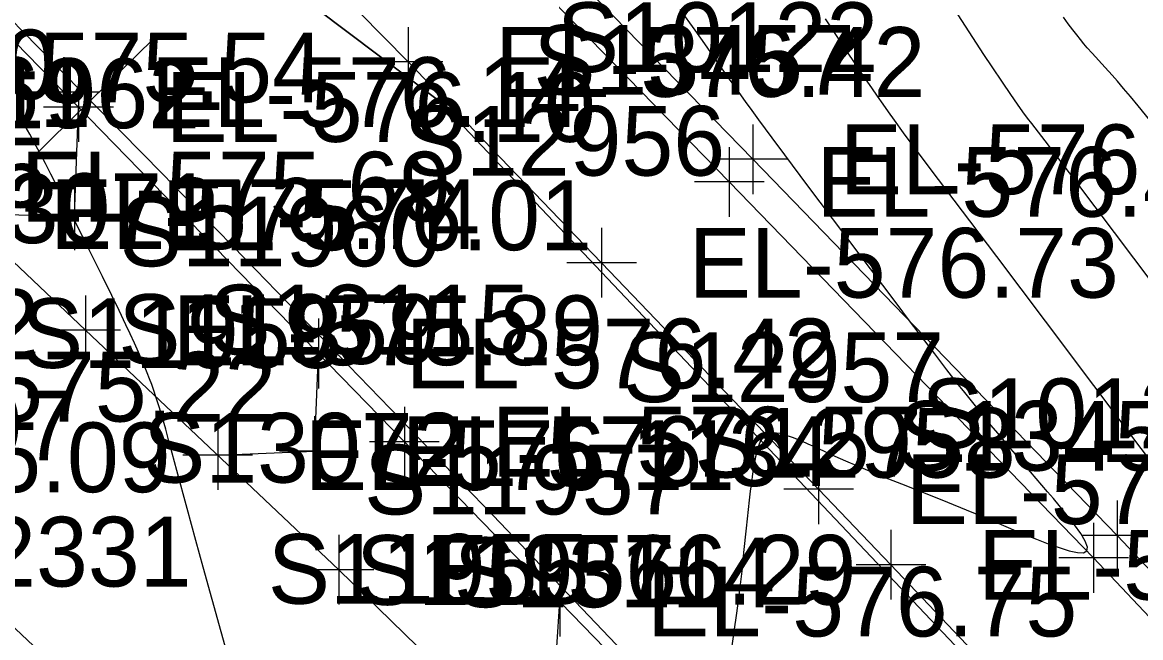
# Model space of a CAD drawing. Extents: x 1729869 to 1735532, y 648588 to 653771.
# Drawn here: x 1731155.8 to 1731220, y 652078.5 to 652113.8 of the extents above; entities that cross this region are included whole.
import ezdxf

# ---------------------------------------------------------------- set-up
doc = ezdxf.new("R2010")
doc.units = 0
for name, color, linetype in [('SURVEY - CENTERLINE - Preliminary', 7, 'Continuous'), ('SURVEY - CENTERLINE - Preliminary Text', 7, 'Continuous'), ('SURVEY - CONTOURS - Index with Text', 7, 'Continuous'), ('SURVEY - CONTOURS - Intermediate with optional Text', 7, 'Continuous'), ('SURVEY - DRAINAGE - Area Shapes', 7, 'Continuous'), ('SURVEY - DRAINAGE - Area Shapes Text', 7, 'Continuous'), ('SURVEY - DRAINAGE - Storm Sewer - Points - Numbers', 7, 'Continuous'), ('SURVEY - DTM - Breaklines', 7, 'Continuous'), ('SURVEY - DTM - Breaklines - Points - Elevations', 7, 'Continuous'), ('SURVEY - DTM - Breaklines - Points - Locators', 7, 'Continuous'), ('SURVEY - DTM - Breaklines - Points - Numbers', 7, 'Continuous'), ('SURVEY - ROADSIDE BARRIERS - Points - Elevations', 7, 'Continuous'), ('SURVEY - TRAFFIC CONTROL - Pavement Marking - Points - Elevations', 7, 'Continuous'), ('SURVEY - TRAFFIC CONTROL - Pavement Marking - Points - Locators', 7, 'Continuous'), ('SURVEY - TRAFFIC CONTROL - Pavement Marking - Points - Numbers', 7, 'Continuous'), ('SURVEY - TRAFFIC CONTROL - Pavement Marking with Text', 7, 'Continuous'), ('SURVEY - TRANSPORTATION - Features', 7, 'Continuous'), ('SURVEY - TRANSPORTATION - Features - Points - Elevations', 7, 'Continuous'), ('SURVEY - TRANSPORTATION - Features - Points - Locators', 7, 'Continuous'), ('SURVEY - TRANSPORTATION - Features - Points - Numbers', 7, 'Continuous'), ('SURVEY - TRANSPORTATION - Roads', 7, 'Continuous'), ('SURVEY - TRANSPORTATION - Roads - Points - Elevations', 7, 'Continuous'), ('SURVEY - TRANSPORTATION - Roads - Points - Locators', 7, 'Continuous'), ('SURVEY - TRANSPORTATION - Roads - Points - Numbers', 7, 'Continuous')]:
    doc.layers.add(name, color=color, linetype=linetype)

msp = doc.modelspace()

# ---------------------------------------------------------------- linework, layer by layer
at = {"layer": 'SURVEY - CENTERLINE - Preliminary'}
msp.add_arc((1729018.342, 650008.232), 3000, 36.727042, 45.05905, dxfattribs=at)
at = {"layer": 'SURVEY - CENTERLINE - Preliminary Text'}
for q in [(1731163.301, 652112.792), (1731156.164, 652105.788)]:
    msp.add_line((1731159.733, 652109.29), q, dxfattribs=at)
at = {"layer": 'SURVEY - CONTOURS - Index with Text'}
msp.add_lwpolyline([(1731222.414, 652105.812), (1731219.833, 652108.997), (1731219.393, 652109.525), (1731218.999, 652109.991), (1731218.647, 652110.4), (1731218.34, 652110.75), (1731217.94, 652111.196), (1731217.201, 652112.002), (1731216.919, 652112.319), (1731216.727, 652112.543), (1731216.526, 652112.786), (1731216.313, 652113.053), (1731216.082, 652113.354), (1731215.832, 652113.69), (1731215.559, 652114.066)], dxfattribs=at)
at = {"layer": 'SURVEY - CONTOURS - Intermediate with optional Text'}
for points in [[(1731196.464, 652077.466), (1731196.703, 652079.098), (1731196.778, 652079.617), (1731196.891, 652080.442), (1731196.97, 652081.069), (1731197.044, 652081.694), (1731197.128, 652082.456), (1731197.22, 652083.365), (1731197.36, 652084.758), (1731197.415, 652085.295), (1731197.474, 652085.832), (1731197.534, 652086.363), (1731197.598, 652086.885), (1731197.664, 652087.391), (1731197.734, 652087.878), (1731197.789, 652088.231), (1731197.848, 652088.568), (1731197.879, 652088.729), (1731197.911, 652088.886), (1731197.978, 652089.168), (1731198.053, 652089.426), (1731198.14, 652089.657), (1731198.241, 652089.855), (1731198.358, 652090.017), (1731198.495, 652090.136), (1731198.624, 652090.202), (1731198.767, 652090.239), (1731198.924, 652090.25), (1731199.093, 652090.238), (1731199.273, 652090.207), (1731199.464, 652090.16), (1731199.575, 652090.127), (1731199.689, 652090.09), (1731199.805, 652090.049), (1731200.047, 652089.959), (1731200.172, 652089.909), (1731200.518, 652089.766), (1731200.879, 652089.609), (1731201.255, 652089.441), (1731202.437, 652088.901), (1731203.052, 652088.627), (1731203.677, 652088.355), (1731204.311, 652088.087), (1731204.789, 652087.89), (1731205.272, 652087.695), (1731206.253, 652087.306), (1731208.007, 652086.613), (1731208.908, 652086.251), (1731209.976, 652085.814), (1731211.092, 652085.351), (1731212.829, 652084.62), (1731213.613, 652084.295), (1731214.004, 652084.137), (1731214.673, 652083.876), (1731215.306, 652083.648), (1731215.875, 652083.472), (1731216.35, 652083.369), (1731216.702, 652083.357), (1731216.903, 652083.457), (1731216.931, 652083.684), (1731216.804, 652084.023), (1731216.55, 652084.452), (1731216.195, 652084.952), (1731215.768, 652085.499), (1731215.297, 652086.075), (1731214.974, 652086.46), (1731214.646, 652086.846), (1731213.327, 652088.384), (1731212.927, 652088.853), (1731212.535, 652089.315), (1731212.152, 652089.77), (1731211.779, 652090.218), (1731211.414, 652090.658), (1731211.059, 652091.091), (1731210.657, 652091.586), (1731210.27, 652092.069), (1731209.896, 652092.538), (1731209.537, 652092.993), (1731208.865, 652093.854), (1731208.167, 652094.759), (1731207.215, 652096.007), (1731206.78, 652096.581), (1731205.887, 652097.763), (1731200.886, 652104.406), (1731199.561, 652106.177), (1731198.839, 652107.148), (1731198.072, 652108.191), (1731197.692, 652108.713), (1731197.314, 652109.236), (1731196.938, 652109.761), (1731196.247, 652110.738), (1731194.841, 652112.737), (1731194.423, 652113.326), (1731193.568, 652114.518)], [(1731222.791, 652085.638), (1731214.52, 652096.635), (1731211.724, 652100.351), (1731210.186, 652102.387), (1731207.959, 652105.32), (1731207.174, 652106.363), (1731206.644, 652107.077), (1731206.37, 652107.45), (1731205.85, 652108.168), (1731205.509, 652108.645), (1731205.204, 652109.078), (1731204.885, 652109.535), (1731204.55, 652110.019), (1731204.198, 652110.533), (1731203.827, 652111.08), (1731202.901, 652112.467), (1731201.901, 652113.981)], [(1731231.504, 652084.417), (1731219.588, 652100.253), (1731216.262, 652104.666), (1731215.17, 652106.108), (1731214.495, 652106.99), (1731213.73, 652107.976), (1731213.496, 652108.285), (1731213.231, 652108.644), (1731212.918, 652109.082), (1731212.529, 652109.64), (1731212.046, 652110.35), (1731211.455, 652111.233), (1731210.992, 652111.932), (1731209.502, 652114.207)], [(1731167.742, 652076.973), (1731166.193, 652082.52), (1731165.769, 652084.056), (1731165.268, 652085.89), (1731164.682, 652088.07), (1731164.412, 652089.076), (1731164.226, 652089.765), (1731164.039, 652090.443), (1731163.851, 652091.1), (1731163.665, 652091.723), (1731163.481, 652092.303), (1731163.36, 652092.659), (1731163.238, 652093), (1731163.114, 652093.331), (1731162.975, 652093.684), (1731162.903, 652093.861), (1731162.695, 652094.36), (1731162.474, 652094.869), (1731162.243, 652095.386), (1731162.003, 652095.907), (1731161.758, 652096.431), (1731161.368, 652097.247), (1731160.944, 652098.119), (1731160.407, 652099.209), (1731159.653, 652100.727), (1731158.705, 652102.618), (1731158.064, 652103.885), (1731157.764, 652104.473), (1731157.455, 652105.073), (1731157.139, 652105.679), (1731156.818, 652106.285), (1731156.494, 652106.887), (1731156.237, 652107.356), (1731155.978, 652107.821), (1731155.703, 652108.301)]]:
    msp.add_lwpolyline(points, dxfattribs=at)
at = {"layer": 'SURVEY - DRAINAGE - Area Shapes'}
msp.add_lwpolyline([(1731097.142, 652171.409), (1731011.148, 652256.97), (1730865.03, 652403.158), (1730749.606, 652518.939), (1730781.764, 652550.883), (1730851.291, 652571.58), (1730949.072, 652515.98), (1730982.838, 652438.563), (1731020.351, 652368.14), (1731165.291, 652192.393), (1731281.807, 652137.032), (1731316.797, 652088.672), (1731252.279, 652032.718), (1731179.777, 652109.245)], close=True, dxfattribs=at)
at = {"layer": 'SURVEY - DRAINAGE - Area Shapes Text'}
msp.add_lwpolyline([(1731252.279, 652032.718), (1731252.279, 652032.718), (1731331.927, 651940.868), (1731382.756, 651879.672), (1731447.67, 651794.75), (1731482.093, 651747.619), (1731463.009, 651708.574), (1731417.334, 651769.604), (1731372.727, 651826.43), (1731331.142, 651879.707), (1731270.184, 651948.802), (1731219.221, 652002.428), (1731149.8, 652071.308), (1731071.45, 652144.137), (1731094.843, 652173.647), (1731097.142, 652171.409), (1731179.777, 652109.245)], close=True, dxfattribs=at)
at = {"layer": 'SURVEY - DTM - Breaklines'}
msp.add_lwpolyline([(1731035.462, 652269.556), (1731036.254, 652268.75), (1731049.78, 652255.258), (1731071.01, 652234.055), (1731092.233, 652212.831), (1731113.392, 652191.515), (1731134.61, 652170.281), (1731155.653, 652148.89), (1731176.704, 652127.515), (1731197.722, 652105.922), (1731218.638, 652084.352), (1731239.234, 652062.543), (1731259.779, 652040.444), (1731279.977, 652018.028), (1731278.681, 652016.879)], dxfattribs=at)
at = {"layer": 'SURVEY - DTM - Breaklines - Points - Locators'}
for p, q in [((1731197.722, 652107.922), (1731197.722, 652103.922)), ((1731199.722, 652105.922), (1731195.722, 652105.922)), ((1731218.638, 652086.352), (1731218.638, 652082.352)), ((1731220.638, 652084.352), (1731216.638, 652084.352))]:
    msp.add_line(p, q, dxfattribs=at)
at = {"layer": 'SURVEY - TRAFFIC CONTROL - Pavement Marking - Points - Locators'}
for p, q in [((1731159.036, 652110.921), (1731159.036, 652106.921)), ((1731161.036, 652108.921), (1731157.036, 652108.921)), ((1731158.811, 652104.708), (1731158.811, 652100.708)), ((1731160.811, 652102.708), (1731156.811, 652102.708)), ((1731172.812, 652096.786), (1731172.812, 652092.786)), ((1731174.812, 652094.786), (1731170.812, 652094.786)), ((1731167.023, 652090.956), (1731167.023, 652086.956)), ((1731172.577, 652091.183), (1731172.577, 652087.183)), ((1731169.023, 652088.956), (1731165.023, 652088.956)), ((1731174.577, 652089.183), (1731170.577, 652089.183)), ((1731186.66, 652082.555), (1731186.66, 652078.555)), ((1731188.66, 652080.555), (1731184.66, 652080.555))]:
    msp.add_line(p, q, dxfattribs=at)
at = {"layer": 'SURVEY - TRAFFIC CONTROL - Pavement Marking with Text'}
for points in [[(1731152.399, 652102.776), (1731158.811, 652102.708), (1731159.036, 652108.921)], [(1731167.023, 652088.956), (1731172.577, 652089.183), (1731172.812, 652094.786)], [(1731181.14, 652075.432), (1731186.302, 652075.367), (1731186.66, 652080.555)]]:
    msp.add_lwpolyline(points, dxfattribs=at)
at = {"layer": 'SURVEY - TRANSPORTATION - Features'}
msp.add_lwpolyline([(1731033.434, 652270.024), (1731034.936, 652267.426), (1731048.46, 652253.936), (1731069.689, 652232.733), (1731090.91, 652211.511), (1731112.063, 652190.199), (1731133.28, 652168.968), (1731154.322, 652147.578), (1731175.372, 652126.204), (1731196.374, 652104.628), (1731217.283, 652083.065), (1731237.88, 652061.256), (1731258.402, 652039.18), (1731278.681, 652016.879)], dxfattribs=at)
at = {"layer": 'SURVEY - TRANSPORTATION - Features - Points - Locators'}
for p, q in [((1731196.374, 652106.628), (1731196.374, 652102.628)), ((1731198.374, 652104.628), (1731194.374, 652104.628)), ((1731217.283, 652085.065), (1731217.283, 652081.065)), ((1731219.283, 652083.065), (1731215.283, 652083.065))]:
    msp.add_line(p, q, dxfattribs=at)
at = {"layer": 'SURVEY - TRANSPORTATION - Roads'}
for points in [[(1731241.27, 651992.69), (1731223.347, 652011.521), (1731199.624, 652035.873), (1731178.27, 652056.939), (1731168.217, 652066.679), (1731158.163, 652076.419), (1731140.702, 652092.881), (1731127.539, 652105.157), (1731108.457, 652122.813), (1731083.234, 652145.604), (1731065.183, 652161.415), (1731056.096, 652169.25), (1731043.894, 652179.597), (1731028.642, 652192.531), (1730997.607, 652217.755), (1730969.266, 652239.947), (1730932.567, 652267.672), (1730908.358, 652285.385), (1730872.323, 652310.622), (1730852.595, 652324.285), (1730842.714, 652331.091), (1730807.686, 652354.257)], [(1731283.394, 651975.645), (1731259.51, 652002.579), (1731252.817, 652010.007), (1731242.05, 652021.841), (1731236.611, 652027.706), (1731232.532, 652032.105), (1731225.713, 652039.419), (1731214.299, 652051.538), (1731203.18, 652063.38), (1731191.811, 652075.231), (1731177.736, 652089.726), (1731158.199, 652109.78), (1731151.218, 652116.94), (1731121.781, 652146.893), (1731097.861, 652171.053), (1731071.042, 652197.973)], [(1731092.244, 652198.318), (1731110.548, 652179.854), (1731142.862, 652147.122), (1731152.688, 652137.151), (1731159.703, 652130.027), (1731177.944, 652111.504), (1731189.048, 652099.987), (1731201.505, 652086.997), (1731205.657, 652082.667), (1731240.089, 652046.42), (1731254.968, 652030.216), (1731269.804, 652013.975), (1731291.041, 651990.04)], [(1731072.201, 652175.531), (1731076.714, 652171.579), (1731085.681, 652163.606), (1731099.12, 652151.634), (1731106.542, 652144.934), (1731109.511, 652142.254), (1731121.387, 652131.536), (1731125.84, 652127.515), (1731143.434, 652111.195), (1731150.728, 652104.355), (1731159.448, 652096.114), (1731173.982, 652082.379), (1731189.738, 652067.029), (1731209.701, 652047.399), (1731220.979, 652036.052), (1731226.59, 652030.351), (1731240.437, 652015.923), (1731244.586, 652011.589), (1731251.47, 652004.337), (1731256.919, 651998.481), (1731269.179, 651985.304)]]:
    msp.add_lwpolyline(points, dxfattribs=at)
at = {"layer": 'SURVEY - TRANSPORTATION - Roads - Points - Locators'}
for p, q in [((1731177.944, 652113.504), (1731177.944, 652109.504)), ((1731158.199, 652111.78), (1731158.199, 652107.78)), ((1731179.944, 652111.504), (1731175.944, 652111.504)), ((1731160.199, 652109.78), (1731156.199, 652109.78)), ((1731189.048, 652101.987), (1731189.048, 652097.987)), ((1731191.048, 652099.987), (1731187.048, 652099.987)), ((1731159.448, 652098.114), (1731159.448, 652094.114)), ((1731161.448, 652096.114), (1731157.448, 652096.114)), ((1731177.736, 652091.726), (1731177.736, 652087.726)), ((1731179.736, 652089.726), (1731175.736, 652089.726)), ((1731201.505, 652088.997), (1731201.505, 652084.997)), ((1731203.505, 652086.997), (1731199.505, 652086.997)), ((1731173.982, 652084.379), (1731173.982, 652080.379)), ((1731205.657, 652084.667), (1731205.657, 652080.667)), ((1731207.657, 652082.667), (1731203.657, 652082.667)), ((1731175.982, 652082.379), (1731171.982, 652082.379))]:
    msp.add_line(p, q, dxfattribs=at)

# ---------------------------------------------------------------- texts
at = {"layer": 'SURVEY - DRAINAGE - Storm Sewer - Points - Numbers'}
msp.add_text('S397', height=4, dxfattribs=at).set_placement((1731146.324, 652088.655))
msp.add_text('S397', height=4, dxfattribs=at).set_placement((1731146.324, 652088.655))
at = {"layer": 'SURVEY - DTM - Breaklines - Points - Elevations'}
msp.add_text('EL-576.74', height=4, dxfattribs=at).set_placement((1731202.722, 652103.922))
at = {"layer": 'SURVEY - DTM - Breaklines - Points - Numbers'}
for s, p in [('S10122', (1731186.482, 652110.922)), ('S10123', (1731207.398, 652089.352))]:
    msp.add_text(s, height=4, dxfattribs=at).set_placement(p)
at = {"layer": 'SURVEY - ROADSIDE BARRIERS - Points - Elevations'}
for s, p in [('EL-574.92', (1731132.115, 652094.473)), ('EL-575.09', (1731139.64, 652086.828))]:
    msp.add_text(s, height=4, dxfattribs=at).set_placement(p)
at = {"layer": 'SURVEY - TRAFFIC CONTROL - Pavement Marking - Points - Elevations'}
for s, p in [('EL-576.10', (1731164.036, 652106.921)), ('EL-575.74', (1731157.399, 652100.776)), ('EL-576.01', (1731163.811, 652100.708)), ('EL-576.42', (1731177.812, 652092.786)), ('EL-576.11', (1731172.023, 652086.956)), ('EL-576.34', (1731177.577, 652087.183)), ('EL-576.75', (1731191.66, 652078.555))]:
    msp.add_text(s, height=4, dxfattribs=at).set_placement(p)
at = {"layer": 'SURVEY - TRAFFIC CONTROL - Pavement Marking - Points - Numbers'}
for s, p in [('S11961', (1731141.317, 652107.776)), ('S11962', (1731147.571, 652107.708)), ('S11960', (1731161.399, 652099.786)), ('S11958', (1731155.736, 652093.956)), ('S11959', (1731161.322, 652094.183)), ('S11957', (1731175.42, 652085.555)), ('S11955', (1731169.9, 652080.432)), ('S11956', (1731174.952, 652080.367))]:
    msp.add_text(s, height=4, dxfattribs=at).set_placement(p)
at = {"layer": 'SURVEY - TRANSPORTATION - Features - Points - Elevations'}
msp.add_text('EL-576.41', height=4, dxfattribs=at).set_placement((1731201.374, 652102.628))
at = {"layer": 'SURVEY - TRANSPORTATION - Features - Points - Numbers'}
for s, p in [('S13457', (1731185.134, 652109.628)), ('S13458', (1731205.996, 652088.065))]:
    msp.add_text(s, height=4, dxfattribs=at).set_placement(p)
at = {"layer": 'SURVEY - TRANSPORTATION - Roads - Points - Elevations'}
for s, p in [('EL-576.42', (1731182.944, 652109.504)), ('EL-575.54', (1731148.434, 652109.195)), ('EL-576.14', (1731163.199, 652107.78)), ('EL-574.95', (1731132.539, 652103.157)), ('EL-575.69', (1731155.728, 652102.355)), ('EL-576.73', (1731194.048, 652097.987)), ('EL-575.89', (1731164.448, 652094.114)), ('EL-575.22', (1731145.702, 652090.881)), ('EL-576.57', (1731182.736, 652087.726)), ('EL-577.09', (1731206.505, 652084.997)), ('EL-576.29', (1731178.982, 652080.379)), ('EL-577.21', (1731210.657, 652080.667))]:
    msp.add_text(s, height=4, dxfattribs=at).set_placement(p)
at = {"layer": 'SURVEY - TRANSPORTATION - Roads - Points - Numbers'}
for s, p in [('S13070', (1731139.315, 652109.355)), ('S12956', (1731177.698, 652104.987)), ('S13071', (1731148.366, 652101.114)), ('S13115', (1731166.496, 652094.726)), ('S12957', (1731190.265, 652091.997)), ('S13072', (1731162.742, 652087.379)), ('S12958', (1731194.37, 652087.667)), ('S12331', (1731147.081, 652081.419)), ('S13114', (1731180.571, 652080.231))]:
    msp.add_text(s, height=4, dxfattribs=at).set_placement(p)

doc.saveas('drawing.dxf')
